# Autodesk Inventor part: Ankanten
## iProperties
Created: 2012-02
Part Number: Ankanten
Document SubType Name: Modellieren
Designer: M.Peppel
Mass: 2004.08 g
Surface Area: 20120.8 cm^2
Volume: 2004.08 cm^3
Density: 1 g/cm^3
Author: M.Peppel
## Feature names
1. Rundung1 [Fillet]
